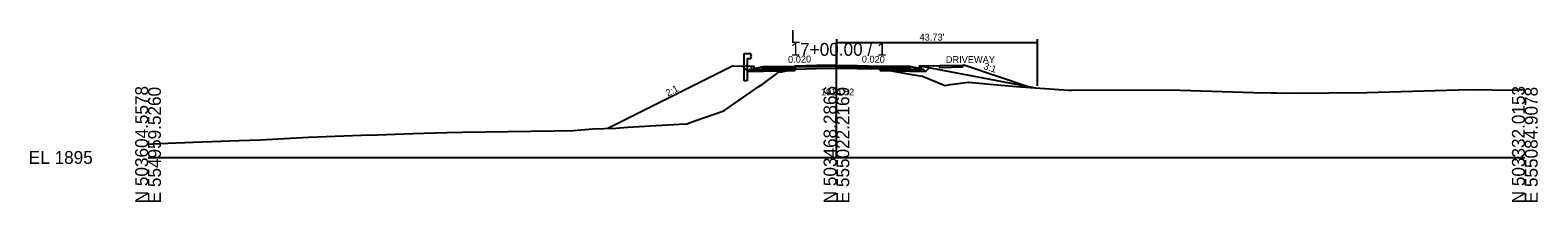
# Model space of a CAD drawing. Extents: x -26 to 4603, y -10 to 4703.
# Drawn here: x -25.7 to 302.8, y 3090.3 to 3127.8 of the extents above; entities that cross this region are included whole.
import ezdxf

# ---------------------------------------------------------------- set-up
doc = ezdxf.new("R2010")
doc.units = 0
for name, color, linetype in [('Default', 7, 'Continuous'), ('Exist Cross Section Cell', 7, 'Continuous'), ('Exist XS Ground Line', 7, 'Continuous'), ('Prop CMT Guardrail Graphics', 7, 'Continuous'), ('Prop CMT Pvmt Course 1', 7, 'Continuous'), ('Prop CMT Pvmt Course 2', 7, 'Continuous'), ('Prop CMT Pvmt Course 3', 7, 'Continuous'), ('Prop CMT Pvmt Milling', 7, 'Continuous'), ('Prop CMT Shear Line', 7, 'Continuous'), ('Prop CMT Shld Paved Course 2', 7, 'Continuous'), ('Prop CMT Shld Paved Course 3', 7, 'Continuous'), ('Prop CMT Subgrade Earthwork', 7, 'Continuous'), ('Prop Conc Curb and Gutter', 7, 'Continuous'), ('Prop Corridor Mesh Bottom', 7, 'Continuous'), ('Prop XS Finish Grade', 7, 'Continuous'), ('Prop XS Label Text', 7, 'Continuous'), ('Prop XS SS Elevation Text', 7, 'Continuous'), ('Scratch_Level_0', 7, 'Continuous'), ('Scratch_Level_9', 7, 'Continuous')]:
    doc.layers.add(name, color=color, linetype=linetype)

msp = doc.modelspace()

# ---------------------------------------------------------------- linework, layer by layer
at = {"layer": 'Exist Cross Section Cell'}
for p, q in [((150, 3100), (150, 3125)), ((0, 3100), (150, 3100)), ((150, 3100), (300, 3100))]:
    msp.add_line(p, q, dxfattribs=at)
at = {"layer": 'Exist XS Ground Line'}
msp.add_lwpolyline([(0, 3102.92), (2.49, 3103.02), (9.8, 3103.32), (19.87, 3103.68), (24.51, 3103.87), (34.95, 3104.41), (46.52, 3104.84), (50.03, 3104.93), (57.66, 3105.2), (65.11, 3105.46), (68.54, 3105.51), (88.41, 3105.84), (92.69, 3105.88), (96.82, 3106.24), (101.92, 3106.42), (104.56, 3106.59), (108.25, 3106.8), (115.73, 3107.26), (117.37, 3107.33), (119.37, 3108.09), (125.49, 3110.21), (133.12, 3115.49), (133.78, 3115.92), (137.49, 3118.66), (138.03, 3118.7), (140.97, 3119.28), (145.62, 3119.41), (149.93, 3119.52), (154.52, 3119.43), (159.53, 3119.32), (166.44, 3118.14), (168.72, 3117.76), (172.95, 3116.02), (173.67, 3115.72), (174.78, 3115.92), (178.78, 3116.45), (185.88, 3115.77), (189.19, 3115.47), (200.59, 3114.69), (200.81, 3114.68), (201.22, 3114.68), (222.64, 3114.75), (240.89, 3114.18), (244.66, 3114.14), (246.05, 3114.09), (249.07, 3114.03), (265.59, 3114.19), (278.03, 3114.57), (287.93, 3114.81), (292.92, 3114.73), (293.9, 3114.72), (298.8, 3114.76), (300, 3114.83)], dxfattribs=at)
at = {"layer": 'Prop CMT Guardrail Graphics'}
for points in [[(129.89, 3116.71), (129.89, 3122.71)], [(129.89, 3122.71), (131.23, 3122.71), (131.5, 3122.41)], [(131.5, 3121.83), (131.23, 3121.54), (130.56, 3121.54)], [(130.56, 3121.54), (130.56, 3116.71)], [(131.5, 3122.41), (131.23, 3122.12)], [(131.23, 3122.12), (131.5, 3121.83)], [(130.56, 3116.71), (129.89, 3116.71)]]:
    msp.add_lwpolyline(points, dxfattribs=at)
at = {"layer": 'Prop CMT Pvmt Course 1'}
for points in [[(134, 3119.83), (140.97, 3119.96), (140.97, 3119.71), (140.97, 3119.71), (134, 3119.58), (134, 3119.58), (134, 3119.58), (134, 3119.83), (134, 3119.83)], [(149.93, 3120.14), (145.62, 3120.06), (145.62, 3120.06), (140.97, 3119.96), (140.97, 3119.96), (140.97, 3119.28), (140.97, 3119.28), (140.97, 3119.28), (145.62, 3119.41), (145.62, 3119.41), (149.93, 3119.52), (150, 3119.52), (150, 3119.52), (150, 3119.52), (150, 3120.15), (149.93, 3120.14), (149.93, 3120.14)], [(159.53, 3119.95), (159.53, 3119.32), (159.53, 3119.32), (159.53, 3119.32), (154.52, 3119.43), (154.52, 3119.43), (150, 3119.52), (150, 3119.52), (150, 3120.15), (154.52, 3120.06), (154.52, 3120.06), (159.53, 3119.95), (159.53, 3119.95)], [(166, 3119.83), (159.53, 3119.95), (159.53, 3119.7), (159.53, 3119.7), (166, 3119.58), (166, 3119.58), (166, 3119.58), (166, 3119.83), (166, 3119.83)]]:
    msp.add_lwpolyline(points, dxfattribs=at)
at = {"layer": 'Prop CMT Pvmt Course 2'}
for points in [[(134, 3119.58), (140.97, 3119.71), (140.97, 3119.38), (140.97, 3119.38), (134, 3119.24), (134, 3119.24), (134, 3119.24), (134, 3119.58), (134, 3119.58)], [(166, 3119.58), (159.53, 3119.7), (159.53, 3119.37), (159.53, 3119.37), (166, 3119.24), (166, 3119.24), (166, 3119.24), (166, 3119.58), (166, 3119.58)]]:
    msp.add_lwpolyline(points, dxfattribs=at)
at = {"layer": 'Prop CMT Pvmt Course 3'}
for points in [[(134, 3119.24), (140.97, 3119.38), (140.97, 3119.01), (140.97, 3119.01), (134, 3118.87), (134, 3118.87), (134, 3118.87), (134, 3119.24), (134, 3119.24)], [(166, 3119.24), (159.53, 3119.37), (159.53, 3119), (159.53, 3119), (166, 3118.87), (166, 3118.87), (166, 3118.87), (166, 3119.24), (166, 3119.24)], [(169, 3119.18), (166, 3119.24), (166, 3118.87), (166, 3118.87), (169.38, 3118.8), (169.38, 3118.8), (169.38, 3118.8), (169, 3119.18), (169, 3119.18)]]:
    msp.add_lwpolyline(points, dxfattribs=at)
at = {"layer": 'Prop CMT Pvmt Milling'}
for points in [[(140.97, 3119.28), (140.97, 3119.28), (145.62, 3119.41), (145.62, 3119.41), (149.93, 3119.52), (150, 3119.52), (150, 3119.52)], [(159.53, 3119.32), (159.53, 3119.32), (154.52, 3119.43), (154.52, 3119.43), (150, 3119.52)]]:
    msp.add_lwpolyline(points, dxfattribs=at)
at = {"layer": 'Prop CMT Shld Paved Course 2'}
for points in [[(149.93, 3119.89), (145.62, 3119.81), (145.62, 3119.81), (140.97, 3119.71), (140.97, 3119.71), (140.97, 3119.28), (140.97, 3119.28), (140.97, 3119.28), (145.62, 3119.41), (145.62, 3119.41), (149.93, 3119.52), (150, 3119.52), (150, 3119.52), (150, 3119.52), (150, 3119.9), (149.93, 3119.89), (149.93, 3119.89)], [(159.53, 3119.7), (159.53, 3119.32), (159.53, 3119.32), (159.53, 3119.32), (154.52, 3119.43), (154.52, 3119.43), (150, 3119.52), (150, 3119.52), (150, 3119.9), (154.52, 3119.81), (154.52, 3119.81), (159.53, 3119.7), (159.53, 3119.7)]]:
    msp.add_lwpolyline(points, dxfattribs=at)
at = {"layer": 'Prop CMT Shld Paved Course 3'}
msp.add_lwpolyline([(131, 3119.18), (134, 3119.24), (134, 3118.87), (134, 3118.87), (130.7, 3118.8), (130.7, 3118.8), (130.7, 3118.8), (131, 3119.18), (131, 3119.18)], dxfattribs=at)
at = {"layer": 'Prop CMT Subgrade Earthwork'}
for points in [[(129.54, 3119.96), (130.7, 3118.8), (130.7, 3118.8)], [(130.7, 3118.8), (130.7, 3118.8), (140.97, 3119.01)], [(169.38, 3118.8), (169.38, 3118.8), (159.53, 3119)], [(170.17, 3119.59), (169.38, 3118.8), (169.38, 3118.8)]]:
    msp.add_lwpolyline(points, dxfattribs=at)
at = {"layer": 'Prop Conc Curb and Gutter'}
for points in [[(132, 3119.43), (134, 3119.83), (134, 3119.24), (134, 3119.24), (131.5, 3119.19), (131.5, 3119.19), (131.5, 3119.19), (131.5, 3119.93), (131.5, 3119.93), (132, 3119.93), (132, 3119.43), (132, 3119.43), (132, 3119.43)], [(168, 3119.43), (166, 3119.83), (166, 3119.24), (166, 3119.24), (168.5, 3119.19), (168.5, 3119.19), (168.5, 3119.19), (168.5, 3119.93), (168.5, 3119.93), (168, 3119.93), (168, 3119.43), (168, 3119.43), (168, 3119.43)]]:
    msp.add_lwpolyline(points, dxfattribs=at)
at = {"layer": 'Prop Corridor Mesh Bottom'}
msp.add_lwpolyline([(166, 3119.83), (166, 3119.58)], dxfattribs=at)
at = {"layer": 'Prop XS Finish Grade'}
msp.add_line((168.5, 3119.93), (193.73, 3115.16), dxfattribs=at)
for points in [[(127.5, 3120.01), (100.21, 3106.36)], [(127.5, 3120.01), (131.5, 3119.93), (131.5, 3119.93)]]:
    msp.add_lwpolyline(points, dxfattribs=at)
at = {"layer": 'Prop XS Label Text'}
for p, q in [((150, 3125.79), (150, 3120.49)), ((193.73, 3125), (150, 3125)), ((193.73, 3125.79), (193.73, 3115.63))]:
    msp.add_line(p, q, dxfattribs=at)
at = {"layer": 'Scratch_Level_0'}
for points in [[(172.5, 3120.01), (168.5, 3119.93), (168.5, 3119.93)], [(172.5, 3120.01), (172.5, 3120.01), (172.49, 3119.67), (172.49, 3119.67), (172.49, 3119.67), (177.51, 3119.77), (177.51, 3119.77), (177.5, 3120.11), (172.5, 3120.01)], [(178, 3120.12), (177.5, 3120.11), (177.5, 3120.11)], [(178, 3120.12), (192.66, 3115.23)]]:
    msp.add_lwpolyline(points, dxfattribs=at)
at = {"layer": 'Scratch_Level_9'}
msp.add_lwpolyline([(134, 3119.83), (134, 3119.58)], dxfattribs=at)

# ---------------------------------------------------------------- texts
at = {"layer": 'Default'}
msp.add_text('-', height=0.0001, dxfattribs=at).set_placement((0, 3100))
at = {"layer": 'Exist Cross Section Cell'}
for s, p in [('L', (140, 3125)), ('17+00.00 / 1', (140, 3122.2)), ('EL 1895', (-26, 3098.6))]:
    msp.add_text(s, height=2.8, dxfattribs=at).set_placement(p)
for s, p in [('N 503604.5578', (0, 3090)), ('E 554959.5260', (2.8, 3090)), ('N 503468.2866', (150, 3090)), ('E 555022.2169', (152.8, 3090)), ('N 503332.0153', (300, 3090)), ('E 555084.9078', (302.8, 3090))]:
    msp.add_text(s, height=2.8, rotation=90, dxfattribs=at).set_placement(p)
at = {"layer": 'Prop CMT Shear Line'}
for p in [(127.5, 3120), (129, 3119.97), (129, 3119.97), (132, 3119.42), (134, 3119.82), (134, 3119.82), (150, 3120.14), (166, 3119.82), (166, 3119.82), (168, 3119.42), (192.66, 3115.23), (101.89, 3106.42)]:
    msp.add_text('X', height=0.0025, dxfattribs=at).set_placement(p)
at = {"layer": 'Prop XS Label Text'}
for s, rotation, p in [("43.73'", 0.0969, (168.12, 3125.5)), ('0.020', 1.1458, (139.48, 3120.64)), ('0.020', 358.8542, (155.51, 3120.74)), ('DRIVEWAY', 0.0969, (173.84, 3120.61)), ('2:1', 27.9443, (113.28, 3113.26))]:
    msp.add_text(s, height=1.5, rotation=rotation, dxfattribs=at).set_placement(p)
at = {"layer": 'Prop XS SS Elevation Text'}
msp.add_text('1914.52', height=1.5, dxfattribs=at).set_placement((146.61, 3113.55))
at = {"layer": 'Scratch_Level_0'}
for p in [(172.5, 3120), (177.5, 3120.1), (178, 3120.11)]:
    msp.add_text('X', height=0.0025, dxfattribs=at).set_placement(p)
msp.add_text('3:1', height=1.5, rotation=341.5668, dxfattribs=at).set_placement((181.93, 3119.35))

doc.saveas('drawing.dxf')
